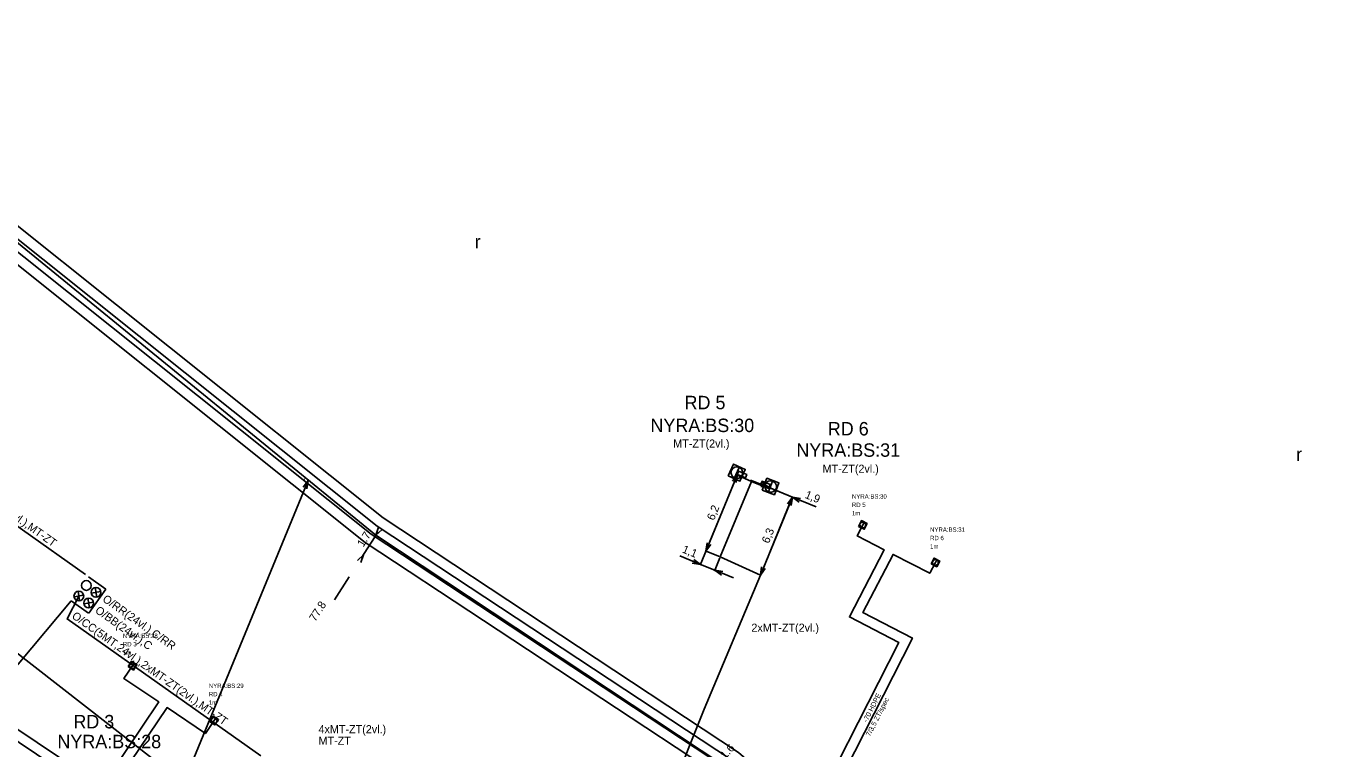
# Model space of a CAD drawing. Extents: x -836739 to -834468, y -1071001 to -1070126.
# Drawn here: x -836438.6 to -836340.8, y -1070360.1 to -1070306.3 of the extents above; entities that cross this region are included whole.
import ezdxf

# ---------------------------------------------------------------- set-up
doc = ezdxf.new("R2010")
doc.units = 0
for name, color, linetype in [('f001_pol_linie', 7, 'Continuous'), ('f001_pol_znacky', 7, 'Continuous'), ('f002_inz_linie_mimo_CETIN', 7, 'Continuous'), ('f003_opt_sit_texty', 7, 'Continuous'), ('f003_opt_sit_znacky', 7, 'Continuous'), ('f006_osa_trasy', 7, 'Continuous'), ('f006_stp_koty', 7, 'Continuous'), ('f007_rezkynet_linie', 7, 'Continuous'), ('f007_rezkynet_texty', 7, 'Continuous'), ('f007_rezkynet_znacky', 7, 'Continuous'), ('f309_rozvadec_opt', 7, 'Continuous'), ('f309_rozvadec_opt_ann', 7, 'Continuous'), ('f309_trubicka', 7, 'Continuous'), ('f309_trubicka_ann', 7, 'Continuous'), ('f309_trubka', 7, 'Continuous')]:
    doc.layers.add(name, color=color, linetype=linetype)

msp = doc.modelspace()

# ---------------------------------------------------------------- linework, layer by layer
at = {"layer": 'f001_pol_linie'}
msp.add_lwpolyline([(-836356.62, -1070406.87), (-836370.19, -1070399.44), (-836385.43, -1070392.2), (-836396.38, -1070386.03), (-836404.41, -1070381.11), (-836409.87, -1070376.61), (-836425.28, -1070363.93), (-836449.03, -1070345.44), (-836455, -1070340), (-836462.64, -1070329.11), (-836464.81, -1070325.47), (-836465.74, -1070321.03), (-836464.89, -1070314.87), (-836461.62, -1070306.74), (-836456.41, -1070297.54), (-836450.95, -1070288.2), (-836447.03, -1070272.79), (-836441.38, -1070260.76)], dxfattribs=at)
at = {"layer": 'f002_inz_linie_mimo_CETIN'}
for points in [[(-836385.68, -1070339.66), (-836385.59, -1070339.43), (-836384.98, -1070339.68), (-836385.07, -1070339.91)], [(-836385.68, -1070339.66), (-836385.59, -1070339.43), (-836384.98, -1070339.68), (-836385.07, -1070339.91)], [(-836385.68, -1070339.66), (-836385.07, -1070339.91)], [(-836385.68, -1070339.66), (-836385.07, -1070339.91)], [(-836383.93, -1070340.4), (-836383.84, -1070340.17), (-836383.23, -1070340.42), (-836383.32, -1070340.65)], [(-836383.93, -1070340.4), (-836383.84, -1070340.17), (-836383.23, -1070340.42), (-836383.32, -1070340.65)], [(-836383.93, -1070340.4), (-836383.32, -1070340.65)], [(-836383.93, -1070340.4), (-836383.32, -1070340.65)]]:
    msp.add_lwpolyline(points, dxfattribs=at)
at = {"layer": 'f003_opt_sit_znacky'}
for p, q in [((-836385.55, -1070339.137), (-836385.91, -1070339.923)), ((-836385.551, -1070339.138), (-836385.55, -1070339.137)), ((-836383.058, -1070340.156), (-836383.362, -1070340.964)), ((-836383.059, -1070340.156), (-836383.058, -1070340.156))]:
    msp.add_line(p, q, dxfattribs=at)
for points in [[(-836386.364, -1070339.768), (-836385.491, -1070340.167), (-836385.092, -1070339.294), (-836385.965, -1070338.895)], [(-836383.826, -1070340.842), (-836382.927, -1070341.179), (-836382.59, -1070340.28), (-836383.489, -1070339.943)]]:
    msp.add_lwpolyline(points, close=True, dxfattribs=at)
for centre, start, end in [((-836385.728, -1070339.531), 65.79663, 245.06903), ((-836385.727, -1070339.532), 245.02828, 65.83652), ((-836383.207, -1070340.561), 69.80775, 249.08016), ((-836383.207, -1070340.561), 249.03941, 69.84764)]:
    msp.add_arc(centre, 0.432, start, end, dxfattribs=at)
at = {"layer": 'f006_osa_trasy'}
for points in [[(-836259.51, -1070422.49), (-836273.33, -1070418.13), (-836279.63, -1070415.33), (-836305.65, -1070405.26), (-836332.15, -1070395.46), (-836355.51, -1070386.15), (-836363.32, -1070381.37), (-836370.68, -1070374.62), (-836386.63, -1070361.4), (-836412.6, -1070344.19), (-836444.52, -1070318.16), (-836450.35, -1070293.64), (-836451.12, -1070284.95), (-836453.47, -1070277.02), (-836456.68, -1070270.62)], [(-836384.62, -1070340.18), (-836385.8, -1070339.68), (-836385.73, -1070339.53)], [(-836399.2, -1070385.59), (-836399.14, -1070384.68), (-836393.13, -1070369.58), (-836388.15, -1070357.15), (-836383.97, -1070347.17), (-836386.96, -1070345.81), (-836384.62, -1070340.18)], [(-836384.62, -1070340.18), (-836383.28, -1070340.74), (-836383.21, -1070340.56)]]:
    msp.add_lwpolyline(points, dxfattribs=at)
at = {"layer": 'f006_stp_koty'}
for p, q in [((-836385.703, -1070339.716), (-836388.452, -1070346.423)), ((-836388.022, -1070345.375), (-836385.68, -1070339.66)), ((-836384.708, -1070340.081), (-836383.32, -1070340.65)), ((-836383.32, -1070340.65), (-836381.589, -1070341.36)), ((-836383.264, -1070340.673), (-836381.533, -1070341.382)), ((-836383.97, -1070347.17), (-836381.589, -1070341.36)), ((-836383.947, -1070347.114), (-836381.566, -1070341.304)), ((-836379.825, -1070342.082), (-836381.589, -1070341.36)), ((-836389.962, -1070345.739), (-836388.429, -1070346.367)), ((-836387.016, -1070345.787), (-836388.078, -1070345.352)), ((-836386.983, -1070345.866), (-836387.389, -1070346.858)), ((-836388.429, -1070346.367), (-836387.367, -1070346.802)), ((-836385.979, -1070347.371), (-836387.367, -1070346.802))]:
    msp.add_line(p, q, dxfattribs=at)
for points in [[(-836435.495, -1070383.458), (-836417.654, -1070340.121)], [(-836418.021, -1070340.618), (-836417.654, -1070340.121), (-836417.743, -1070340.732)], [(-836417.905, -1070340.017), (-836417.932, -1070340.006)], [(-836386.046, -1070340.158), (-836385.68, -1070339.66), (-836385.769, -1070340.272)], [(-836383.818, -1070340.284), (-836383.32, -1070340.65), (-836383.932, -1070340.561)], [(-836381.955, -1070341.858), (-836381.589, -1070341.36), (-836381.677, -1070341.972)], [(-836381.09, -1070341.726), (-836381.589, -1070341.36), (-836380.977, -1070341.448)], [(-836413.695, -1070345.901), (-836412.438, -1070343.937)], [(-836412.15, -1070343.765), (-836412.6, -1070344.19), (-836412.402, -1070343.603)], [(-836387.656, -1070344.876), (-836388.022, -1070345.375), (-836387.933, -1070344.763)], [(-836413.983, -1070346.073), (-836413.534, -1070345.649), (-836413.731, -1070346.235)], [(-836388.927, -1070346.001), (-836388.429, -1070346.367), (-836389.041, -1070346.278)], [(-836386.868, -1070347.169), (-836387.367, -1070346.802), (-836386.755, -1070346.891)], [(-836383.604, -1070346.672), (-836383.97, -1070347.17), (-836383.881, -1070346.558)], [(-836414.594, -1070347.304), (-836415.696, -1070349.012)]]:
    msp.add_lwpolyline(points, dxfattribs=at)
at = {"layer": 'f007_rezkynet_linie'}
for points in [[(-836434.23, -1070347.12), (-836448.346, -1070337.14), (-836447.473, -1070335.438)], [(-836421.168, -1070360.637), (-836435.606, -1070350.43), (-836434.733, -1070348.728)], [(-836435.31, -1070349.07), (-836444.113, -1070359.593)]]:
    msp.add_lwpolyline(points, dxfattribs=at)
at = {"layer": 'f007_rezkynet_znacky'}
for p, q in [((-836432.714, -1070348.208), (-836434.02, -1070347.284)), ((-836434.375, -1070348.666), (-836435.091, -1070348.789)), ((-836434.795, -1070348.37), (-836434.671, -1070349.085)), ((-836434.06, -1070348.889), (-836433.936, -1070349.604)), ((-836433.987, -1070350.01), (-836432.714, -1070348.208)), ((-836433.089, -1070348.387), (-836433.805, -1070348.51)), ((-836433.508, -1070348.091), (-836433.385, -1070348.806)), ((-836435.307, -1070349.077), (-836434.001, -1070350.001)), ((-836433.641, -1070349.185), (-836434.356, -1070349.308))]:
    msp.add_line(p, q, dxfattribs=at)
for centre in [(-836434.174, -1070347.935), (-836434.733, -1070348.728), (-836433.999, -1070349.247), (-836433.447, -1070348.449)]:
    msp.add_circle(centre, 0.363, dxfattribs=at)
at = {"layer": 'f309_rozvadec_opt'}
for p, q in [((-836376.243, -1070343.236), (-836376.441, -1070343.62)), ((-836376.243, -1070343.237), (-836376.243, -1070343.236)), ((-836370.834, -1070346.027), (-836371.032, -1070346.411)), ((-836370.834, -1070346.028), (-836370.834, -1070346.027)), ((-836430.617, -1070353.731), (-836430.858, -1070354.09)), ((-836430.617, -1070353.731), (-836430.617, -1070353.731)), ((-836424.538, -1070357.813), (-836424.779, -1070358.172)), ((-836424.538, -1070357.813), (-836424.538, -1070357.813))]:
    msp.add_line(p, q, dxfattribs=at)
for points in [[(-836376.665, -1070343.532), (-836376.238, -1070343.752), (-836376.018, -1070343.326), (-836376.444, -1070343.106)], [(-836371.256, -1070346.323), (-836370.829, -1070346.543), (-836370.609, -1070346.117), (-836371.035, -1070345.896)], [(-836431.069, -1070353.976), (-836430.671, -1070354.244), (-836430.403, -1070353.845), (-836430.802, -1070353.578)], [(-836424.99, -1070358.058), (-836424.592, -1070358.326), (-836424.324, -1070357.927), (-836424.723, -1070357.66)]]:
    msp.add_lwpolyline(points, close=True, dxfattribs=at)
for centre, start, end in [((-836376.341, -1070343.429), 63.06783, 242.34023), ((-836376.341, -1070343.429), 242.29949, 63.10772), ((-836370.932, -1070346.22), 63.04083, 242.31324), ((-836370.932, -1070346.22), 242.27249, 63.08073), ((-836430.736, -1070353.911), 56.49524, 235.76764), ((-836430.736, -1070353.911), 235.7269, 56.53513), ((-836424.657, -1070357.993), 56.46763, 235.74004), ((-836424.657, -1070357.993), 235.69929, 56.50752)]:
    msp.add_arc(centre, 0.216, start, end, dxfattribs=at)
at = {"layer": 'f309_trubicka'}
for points in [[(-836400.273, -1070369.489), (-836402.644, -1070369.527), (-836403.705, -1070372.886), (-836405.907, -1070379.853), (-836406.712, -1070379.55), (-836427.342, -1070367.602), (-836444.526, -1070356.062), (-836464.165, -1070339.032), (-836460.645, -1070334.701), (-836463.961, -1070332.006), (-836463.228, -1070331.103)], [(-836400.273, -1070369.489), (-836403.36, -1070369.301), (-836404.42, -1070372.66), (-836406.384, -1070378.872), (-836406.39, -1070378.87), (-836426.945, -1070366.965), (-836444.07, -1070355.465), (-836463.125, -1070338.941), (-836460.063, -1070335.174), (-836456.969, -1070337.689), (-836456.236, -1070336.787)], [(-836400.273, -1070369.489), (-836389.056, -1070373.818), (-836390.12, -1070377.18), (-836390.197, -1070377.426), (-836387.286, -1070378.986), (-836373.656, -1070352.184), (-836377.341, -1070350.282), (-836374.754, -1070345.274), (-836376.759, -1070344.239), (-836376.341, -1070343.429)], [(-836400.273, -1070369.489), (-836389.771, -1070373.592), (-836390.835, -1070376.954), (-836391.1, -1070377.793), (-836386.965, -1070380.009), (-836372.65, -1070351.86), (-836376.33, -1070349.96), (-836374.088, -1070345.618), (-836371.351, -1070347.031), (-836370.932, -1070346.22)], [(-836400.273, -1070369.489), (-836404.075, -1070369.075), (-836405.135, -1070372.434), (-836406.818, -1070377.756), (-836426.548, -1070366.328), (-836432.585, -1070362.274), (-836428.785, -1070356.615), (-836431.381, -1070354.872), (-836430.736, -1070353.911)], [(-836400.273, -1070369.489), (-836404.79, -1070368.849), (-836405.85, -1070372.208), (-836407.251, -1070376.638), (-836426.151, -1070365.691), (-836431.544, -1070362.069), (-836428.162, -1070357.033), (-836425.302, -1070358.953), (-836424.657, -1070357.993)]]:
    msp.add_lwpolyline(points, dxfattribs=at)
at = {"layer": 'f309_trubka'}
for points in [[(-836454.989, -1070272.319), (-836452.77, -1070276.743), (-836450.38, -1070284.809), (-836449.608, -1070293.52), (-836449.436, -1070294.242), (-836443.91, -1070317.483), (-836412.074, -1070342.908), (-836385.592, -1070360.377), (-836362.275, -1070380.609), (-836354.445, -1070384.979), (-836353.838, -1070385.201), (-836331.612, -1070394.06), (-836305.12, -1070403.858), (-836279.054, -1070413.944), (-836272.798, -1070416.724), (-836261.073, -1070420.421)], [(-836457, -1070273.327), (-836454.87, -1070277.574), (-836452.6, -1070285.232), (-836451.834, -1070293.88), (-836451.663, -1070294.602), (-836445.92, -1070318.758), (-836413.397, -1070344.729), (-836386.954, -1070362.174), (-836363.574, -1070382.46), (-836355.387, -1070387.031), (-836354.642, -1070387.304), (-836332.419, -1070396.16), (-836305.915, -1070405.961), (-836279.918, -1070416.023), (-836273.596, -1070418.833), (-836262.401, -1070422.363)], [(-836456.329, -1070272.991), (-836454.17, -1070277.297), (-836451.86, -1070285.091), (-836451.092, -1070293.76), (-836445.25, -1070318.333), (-836412.956, -1070344.122), (-836386.5, -1070361.575), (-836363.141, -1070381.843), (-836355.073, -1070386.347), (-836354.374, -1070386.603), (-836332.15, -1070395.46), (-836305.65, -1070405.26), (-836279.63, -1070415.33), (-836273.33, -1070418.13), (-836262.175, -1070421.648)], [(-836261.299, -1070421.137), (-836273.064, -1070417.427), (-836279.342, -1070414.637), (-836305.385, -1070404.559), (-836331.881, -1070394.76), (-836354.106, -1070385.902), (-836354.759, -1070385.663), (-836362.708, -1070381.226), (-836386.046, -1070360.976), (-836412.515, -1070343.515), (-836444.58, -1070317.908), (-836450.178, -1070294.362), (-836450.35, -1070293.64), (-836451.12, -1070284.95), (-836453.47, -1070277.02), (-836455.659, -1070272.655)]]:
    msp.add_lwpolyline(points, dxfattribs=at)

# ---------------------------------------------------------------- texts
at = {"layer": 'f001_pol_znacky'}
for p in [(-836405.248, -1070322.832), (-836344.068, -1070338.662)]:
    msp.add_text('r', height=1, dxfattribs=at).set_placement(p)
at = {"layer": 'f003_opt_sit_texty'}
for s, height, p in [('RD 5', 1, (-836389.62, -1070334.81)), ('NYRA:BS:30', 1, (-836392.16, -1070336.51)), ('RD 6', 1, (-836378.95, -1070336.76)), ('MT-ZT(2vl.)', 0.6, (-836390.46, -1070337.66)), ('NYRA:BS:31', 1, (-836381.29, -1070338.35)), ('MT-ZT(2vl.)', 0.6, (-836379.34, -1070339.54)), ('2xMT-ZT(2vl.)', 0.6, (-836384.64, -1070351.38)), ('RD 3', 1, (-836435.14, -1070358.58)), ('4xMT-ZT(2vl.)', 0.6, (-836416.88, -1070358.94)), ('NYRA:BS:28', 1, (-836436.33, -1070360.06)), ('MT-ZT', 0.6, (-836416.88, -1070359.8))]:
    msp.add_text(s, height=height, dxfattribs=at).set_placement(p)
at = {"layer": 'f006_stp_koty'}
for s, rotation, p in [('1,9', 337.71441, (-836380.703, -1070341.398)), ('6,2', 67.71441, (-836387.429, -1070343.135)), ('1.7', 57.37, (-836413.549, -1070345.118)), ('6,3', 67.71441, (-836383.343, -1070344.849)), ('1,1', 337.71441, (-836389.848, -1070345.461)), ('77.8', 57.18, (-836417.121, -1070350.669)), ('1.6', 47.78, (-836386.586, -1070360.905))]:
    msp.add_text(s, height=0.6, rotation=rotation, dxfattribs=at).set_placement(p)
at = {"layer": 'f007_rezkynet_texty'}
for s, p in [('O/CC(5MT,24vl.),2xMT-ZT(2vl.),MT-ZT', (-836448.046, -1070337.038)), ('O/RR(24vl.),C/RR', (-836433.025, -1070349.067)), ('O/BB(24vl.),C', (-836433.575, -1070349.912)), ('O/CC(5MT,24vl.),2xMT-ZT(2vl.),MT-ZT', (-836435.306, -1070350.328))]:
    msp.add_text(s, height=0.6, rotation=324.74503, dxfattribs=at).set_placement(p)
at = {"layer": 'f309_rozvadec_opt_ann'}
for s, p in [('NYRA:BS:30', (-836377.15, -1070341.467)), ('RD 5', (-836377.15, -1070342.092)), ('1m', (-836377.15, -1070342.717)), ('NYRA:BS:31', (-836371.33, -1070343.938)), ('1m', (-836371.33, -1070345.188)), ('RD 6', (-836371.33, -1070344.562)), ('NYRA:BS:28', (-836431.45, -1070351.847)), ('1m', (-836431.45, -1070353.097)), ('RD 3', (-836431.45, -1070352.472)), ('NYRA:BS:29', (-836425.05, -1070355.568)), ('1m', (-836425.05, -1070356.818)), ('RD 4', (-836425.05, -1070356.193))]:
    msp.add_text(s, height=0.325, dxfattribs=at).set_placement(p)
at = {"layer": 'f309_trubicka_ann'}
for s, p in [('-70 HDPE', (-836376.022, -1070358.159)), ('7/3,5 ZT/spec', (-836375.801, -1070359.214))]:
    msp.add_text(s, height=0.375, rotation=63.04467, dxfattribs=at).set_placement(p)

doc.saveas('drawing.dxf')
